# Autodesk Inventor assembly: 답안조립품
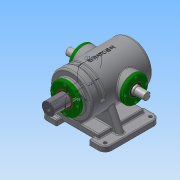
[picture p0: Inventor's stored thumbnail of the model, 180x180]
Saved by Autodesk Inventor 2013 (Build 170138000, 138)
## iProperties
Created: 2018-06
Part Number: 답안조립품
Document SubType Name: Assembly
Designer: Administrator
Author: Administrator
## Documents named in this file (13)
- C:\Users\Administrator\Desktop\380628V1005\답안조립품.iam
- C:\Users\Administrator\Desktop\380628V1005\본체.ipt
- C:\Users\Administrator\Desktop\380628V1005\가변스프링.ipt
- C:\Users\Administrator\Desktop\380628V1005\베어링 6205.ipt
- 베어링 6205.ipt
- C:\Users\Administrator\Desktop\380628V1005\볼트 M4.ipt
- C:\Users\Administrator\Desktop\380628V1005\부시.ipt
- C:\Users\Administrator\Desktop\380628V1005\슬라이드 커버.ipt
- C:\Users\Administrator\Desktop\380628V1005\슬라이드.ipt
- C:\Users\Administrator\Desktop\380628V1005\오일실.ipt
- 오일실.ipt
- C:\Users\Administrator\Desktop\380628V1005\축 커버.ipt
- C:\Users\Administrator\Desktop\380628V1005\편심축.ipt
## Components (1 placed, 1 different names)
1. 가변스프링:1
